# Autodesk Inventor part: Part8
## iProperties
Shininess: 77.0
Length Units: 11269
Angle Units: 11279
Time Units: 11290
Mass Units: 11283
Length Display Precision: 3
Angle Display Precision: 2
Created: 2002-01
Part Number: Part8
Document SubType Name: Modeling
Designer: ***
Density: 0.0
Volumn: 0.0
Area: 0.0
PropertySet Name: Model Information
Control State: 0
Master: False
Checked Out: False
Author: ***
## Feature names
1. Extrusion1
